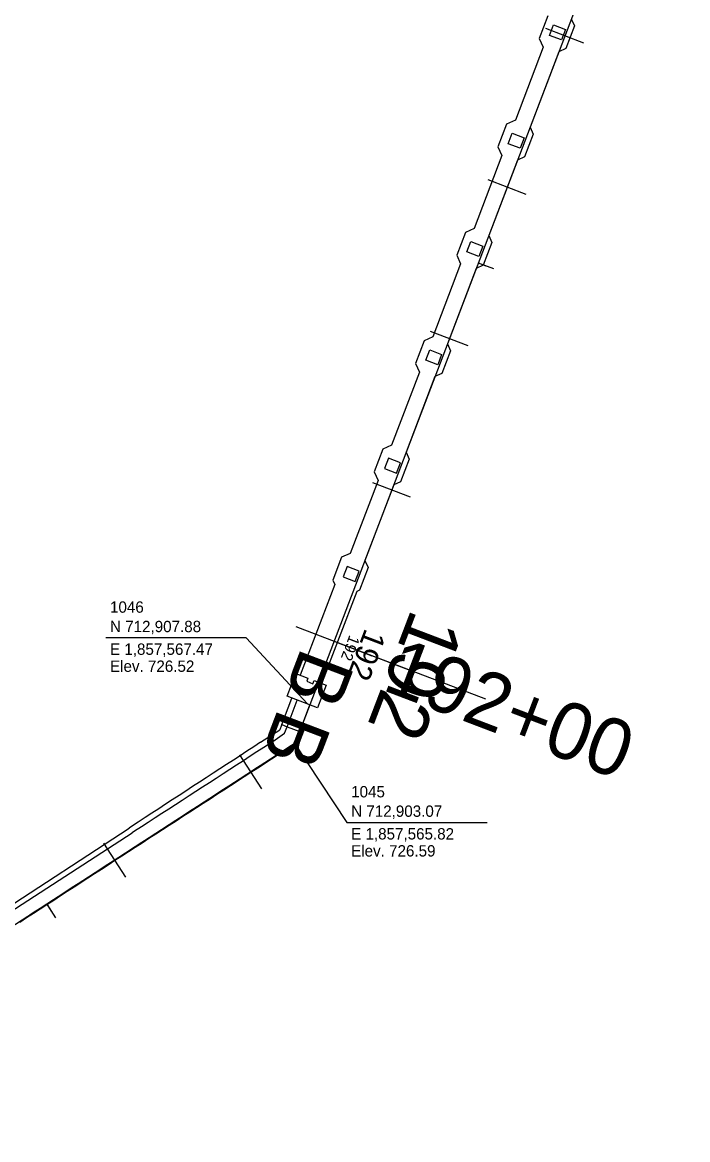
# Model space of a CAD drawing. Extents: x 1823824 to 1861612, y 706975 to 726130.
# Drawn here: x 1826063.6 to 1826145.7, y 712891 to 713028.9 of the extents above; entities that cross this region are included whole.
import ezdxf

# ---------------------------------------------------------------- set-up
doc = ezdxf.new("R2010")
doc.units = 0
for name, color, linetype in [('DR_X_Flood_Boundary', 7, 'Continuous'), ('GE_X_CL_10', 7, 'Continuous'), ('GE_X_CL_100', 7, 'Continuous'), ('GE_X_CL_20', 7, 'Continuous'), ('GE_X_CL_200', 7, 'Continuous'), ('GE_X_CL_50', 7, 'Continuous'), ('SC_Scratch1', 7, 'Continuous'), ('SC_Scratch5', 7, 'Continuous'), ('SC_Scratch6', 7, 'Continuous')]:
    doc.layers.add(name, color=color, linetype=linetype)

msp = doc.modelspace()

# ---------------------------------------------------------------- linework, layer by layer
at = {"layer": 'DR_X_Flood_Boundary'}
for p, q in [((1826145.66, 713067.04), (1826100.09, 712947.43)), ((1826100.09, 712947.43), (1826097.23, 712939.91)), ((1826097.23, 712939.91), (1826021.74, 712890.95))]:
    msp.add_line(p, q, dxfattribs=at)
at = {"layer": 'GE_X_CL_10'}
for p, q in [((1826119.82, 712999.21), (1826120.75, 712998.85)), ((1826102.02, 712952.48), (1826102.95, 712952.13)), ((1826066.57, 712920.02), (1826067.11, 712919.18))]:
    msp.add_line(p, q, dxfattribs=at)
at = {"layer": 'GE_X_CL_100'}
msp.add_line((1826102.02, 712952.48), (1826111.36, 712948.92), dxfattribs=at)
at = {"layer": 'GE_X_CL_20'}
for p, q in [((1826119.82, 712999.21), (1826121.69, 712998.5)), ((1826102.02, 712952.48), (1826103.89, 712951.77)), ((1826066.57, 712920.02), (1826067.66, 712918.35))]:
    msp.add_line(p, q, dxfattribs=at)
at = {"layer": 'GE_X_CL_200'}
msp.add_line((1826102.02, 712952.48), (1826120.71, 712945.36), dxfattribs=at)
at = {"layer": 'GE_X_CL_50'}
msp.add_line((1826102.02, 712952.48), (1826106.69, 712950.7), dxfattribs=at)
at = {"layer": 'SC_Scratch1'}
for p, q in [((1826128.42, 713029.71), (1826127.35, 713026.91)), ((1826128.61, 713027.29), (1826129.1, 713028.58)), ((1826129.1, 713028.58), (1826130.58, 713028.02)), ((1826130.58, 713028.02), (1826130.09, 713026.73)), ((1826131.69, 713028.46), (1826130.62, 713025.66)), ((1826131.3, 713029.32), (1826131.69, 713028.46)), ((1826127.35, 713026.91), (1826127.83, 713025.83)), ((1826130.09, 713026.73), (1826128.61, 713027.29)), ((1826127.83, 713025.83), (1826124.4, 713016.82)), ((1826129.76, 713025.27), (1826126.21, 713015.95)), ((1826130.62, 713025.66), (1826129.76, 713025.27)), ((1826123.32, 713016.34), (1826122.25, 713013.53)), ((1826124.4, 713016.82), (1826123.32, 713016.34)), ((1826126.21, 713015.95), (1826126.59, 713015.09)), ((1826123.52, 713013.92), (1826124, 713015.21)), ((1826124, 713015.21), (1826125.48, 713014.64)), ((1826125.48, 713014.64), (1826124.99, 713013.36)), ((1826126.59, 713015.09), (1826125.52, 713012.29)), ((1826122.25, 713013.53), (1826122.74, 713012.46)), ((1826124.99, 713013.36), (1826123.52, 713013.92)), ((1826122.74, 713012.46), (1826119.3, 713003.45)), ((1826124.66, 713011.9), (1826121.11, 713002.58)), ((1826125.52, 713012.29), (1826124.66, 713011.9)), ((1826119.3, 713003.45), (1826118.23, 713002.96)), ((1826118.23, 713002.96), (1826117.16, 713000.16)), ((1826118.42, 713000.55), (1826118.91, 713001.83)), ((1826118.91, 713001.83), (1826120.39, 713001.27)), ((1826121.11, 713002.58), (1826121.5, 713001.72)), ((1826119.9, 712999.99), (1826118.42, 713000.55)), ((1826120.39, 713001.27), (1826119.9, 712999.99)), ((1826121.5, 713001.72), (1826120.43, 712998.92)), ((1826117.64, 712999.09), (1826114.21, 712990.07)), ((1826117.16, 713000.16), (1826117.64, 712999.09)), ((1826119.57, 712998.53), (1826116.02, 712989.21)), ((1826120.43, 712998.92), (1826119.57, 712998.53)), ((1826113.13, 712989.59), (1826112.06, 712986.79)), ((1826114.21, 712990.07), (1826113.13, 712989.59)), ((1826113.33, 712987.18), (1826113.82, 712988.46)), ((1826113.82, 712988.46), (1826115.3, 712987.9)), ((1826116.4, 712988.35), (1826115.34, 712985.54)), ((1826116.02, 712989.21), (1826116.4, 712988.35)), ((1826112.06, 712986.79), (1826112.55, 712985.71)), ((1826114.81, 712986.61), (1826113.33, 712987.18)), ((1826115.3, 712987.9), (1826114.81, 712986.61)), ((1826112.55, 712985.71), (1826109.11, 712976.7)), ((1826115.34, 712985.54), (1826114.47, 712985.16)), ((1826114.47, 712985.16), (1826110.92, 712975.83)), ((1826108.04, 712976.22), (1826106.97, 712973.42)), ((1826109.11, 712976.7), (1826108.04, 712976.22)), ((1826110.92, 712975.83), (1826111.31, 712974.97)), ((1826108.72, 712975.09), (1826108.23, 712973.8)), ((1826110.2, 712974.53), (1826108.72, 712975.09)), ((1826109.71, 712973.24), (1826110.2, 712974.53)), ((1826111.31, 712974.97), (1826110.24, 712972.17)), ((1826106.97, 712973.42), (1826107.45, 712972.34)), ((1826108.23, 712973.8), (1826109.71, 712973.24)), ((1826107.45, 712972.34), (1826104.02, 712963.33)), ((1826109.38, 712971.78), (1826105.83, 712962.46)), ((1826110.24, 712972.17), (1826109.38, 712971.78)), ((1826104.02, 712963.33), (1826102.94, 712962.85)), ((1826104.02, 712963.33), (1826104.02, 712963.33)), ((1826102.94, 712962.85), (1826101.88, 712960.04)), ((1826105.83, 712962.46), (1826106.22, 712961.6)), ((1826103.63, 712961.72), (1826103.14, 712960.43)), ((1826103.14, 712960.43), (1826104.62, 712959.87)), ((1826105.11, 712961.15), (1826103.63, 712961.72)), ((1826104.62, 712959.87), (1826105.11, 712961.15)), ((1826106.22, 712961.6), (1826105.15, 712958.8)), ((1826102.11, 712959.5), (1826097.85, 712948.29)), ((1826101.88, 712960.04), (1826102.12, 712959.51)), ((1826102.12, 712959.51), (1826102.11, 712959.5)), ((1826104.82, 712958.65), (1826100.49, 712947.28)), ((1826105.15, 712958.8), (1826104.82, 712958.65)), ((1826104.82, 712958.65), (1826104.82, 712958.65)), ((1826096.23, 712945.69), (1826097.3, 712948.49)), ((1826097.3, 712948.49), (1826098.79, 712947.92)), ((1826098.79, 712947.92), (1826098.64, 712947.54)), ((1826098.64, 712947.54), (1826099.4, 712947.25)), ((1826099.4, 712947.25), (1826099.55, 712947.64)), ((1826099.55, 712947.64), (1826101.03, 712947.07)), ((1826101.03, 712947.07), (1826099.97, 712944.26)), ((1826095.56, 712942.2), (1826096.81, 712945.47)), ((1826099.97, 712944.26), (1826096.23, 712945.69)), ((1826096.23, 712941.94), (1826097.47, 712945.21)), ((1826097.79, 712941.35), (1826099.03, 712944.62)), ((1826092.94, 712940.01), (1826095.33, 712941.57)), ((1826094.46, 712940.1), (1826095.91, 712941.12)), ((1826095.91, 712941.12), (1826096.23, 712941.94)), ((1826058.32, 712917.37), (1826076.72, 712929.43)), ((1826058.65, 712916.86), (1826077.1, 712928.84))]:
    msp.add_line(p, q, dxfattribs=at)
for points in [[(1826098.73, 712944.75), (1826091.16, 712952.91), (1826073.85, 712952.91)], [(1826098.73, 712944.75), (1826091.16, 712952.91), (1826073.85, 712952.91)], [(1826097.78, 712941.35), (1826097.75, 712941.27), (1826097.39, 712940.34), (1826097.23, 712939.91), (1826096.77, 712939.61), (1826095.93, 712939.07), (1826095.09, 712938.52), (1826094.25, 712937.98), (1826093.42, 712937.44), (1826092.58, 712936.89), (1826091.74, 712936.35), (1826090.9, 712935.8), (1826090.06, 712935.26), (1826089.22, 712934.72), (1826088.38, 712934.17), (1826087.54, 712933.63), (1826086.7, 712933.08), (1826085.86, 712932.54), (1826085.03, 712931.99), (1826084.19, 712931.45), (1826083.35, 712930.91), (1826082.51, 712930.36), (1826081.67, 712929.82), (1826080.83, 712929.27), (1826079.99, 712928.73), (1826079.15, 712928.19), (1826078.31, 712927.64), (1826077.47, 712927.1), (1826076.64, 712926.55), (1826075.8, 712926.01), (1826074.96, 712925.46), (1826074.12, 712924.92), (1826073.28, 712924.38), (1826072.44, 712923.83), (1826071.6, 712923.29), (1826070.76, 712922.74), (1826069.92, 712922.2), (1826069.08, 712921.66), (1826068.25, 712921.11), (1826067.41, 712920.57), (1826066.57, 712920.02), (1826065.73, 712919.48), (1826064.89, 712918.94), (1826064.05, 712918.39), (1826063.21, 712917.85)], [(1826095.11, 712938.49), (1826095.95, 712939.04), (1826096.79, 712939.58), (1826097.26, 712939.89), (1826097.43, 712940.32), (1826097.78, 712941.26), (1826097.82, 712941.34)], [(1826095.56, 712942.2), (1826095.53, 712942.11), (1826095.33, 712941.57)], [(1826095.56, 712942.2), (1826096.23, 712941.94), (1826097.78, 712941.35), (1826097.81, 712941.34)], [(1826092.94, 712940.01), (1826092.1, 712939.46), (1826091.27, 712938.91), (1826090.43, 712938.36), (1826089.59, 712937.82), (1826088.76, 712937.27), (1826087.92, 712936.72), (1826087.08, 712936.18), (1826086.24, 712935.63), (1826085.4, 712935.09), (1826084.57, 712934.54), (1826083.73, 712933.99), (1826082.89, 712933.45), (1826082.05, 712932.9), (1826081.22, 712932.36), (1826080.38, 712931.81), (1826079.54, 712931.26), (1826078.7, 712930.72), (1826077.86, 712930.17), (1826077.03, 712929.63), (1826076.72, 712929.43)], [(1826094.46, 712940.1), (1826094.19, 712939.92), (1826093.35, 712939.37), (1826092.51, 712938.83), (1826091.67, 712938.28), (1826090.83, 712937.74), (1826090, 712937.2), (1826089.16, 712936.65), (1826088.32, 712936.11), (1826087.48, 712935.56), (1826086.64, 712935.02), (1826085.8, 712934.48), (1826084.96, 712933.93), (1826084.12, 712933.39), (1826083.28, 712932.84), (1826082.44, 712932.3), (1826081.61, 712931.76), (1826080.77, 712931.21), (1826079.93, 712930.67), (1826079.09, 712930.12), (1826078.25, 712929.58), (1826077.41, 712929.03), (1826077.1, 712928.84)], [(1826097.08, 712939.94), (1826103.61, 712930.11), (1826120.92, 712930.11)], [(1826097.08, 712939.94), (1826103.61, 712930.11), (1826120.92, 712930.11)], [(1826063.23, 712917.82), (1826064.07, 712918.37), (1826064.91, 712918.91), (1826065.75, 712919.45), (1826066.58, 712920), (1826067.42, 712920.54), (1826068.26, 712921.09), (1826069.1, 712921.63), (1826069.94, 712922.17), (1826070.78, 712922.72), (1826071.62, 712923.26), (1826072.46, 712923.81), (1826073.3, 712924.35), (1826074.14, 712924.89), (1826074.98, 712925.44), (1826075.81, 712925.98), (1826076.65, 712926.53), (1826077.49, 712927.07), (1826078.33, 712927.61), (1826079.17, 712928.16), (1826080.01, 712928.7), (1826080.85, 712929.25), (1826081.69, 712929.79), (1826082.53, 712930.33), (1826083.37, 712930.88), (1826084.21, 712931.42), (1826085.04, 712931.97), (1826085.88, 712932.51), (1826086.72, 712933.05), (1826087.56, 712933.6), (1826088.4, 712934.14), (1826089.24, 712934.69), (1826090.08, 712935.23), (1826090.92, 712935.77), (1826091.76, 712936.32), (1826092.6, 712936.86), (1826093.44, 712937.4), (1826094.28, 712937.95), (1826095.11, 712938.49)]]:
    msp.add_lwpolyline(points, dxfattribs=at)
at = {"layer": 'SC_Scratch5'}
for points in [[(1826132.83, 713026.35), (1826128.16, 713028.13)], [(1826125.71, 713007.66), (1826121.04, 713009.44)], [(1826118.59, 712988.97), (1826113.92, 712990.75)], [(1826111.47, 712970.28), (1826106.8, 712972.06)], [(1826106.69, 712950.7), (1826097.34, 712954.26)], [(1826093.1, 712934.25), (1826090.38, 712938.45)], [(1826076.32, 712923.37), (1826073.6, 712927.56)]]:
    msp.add_lwpolyline(points, dxfattribs=at)

# ---------------------------------------------------------------- texts
at = {"layer": 'GE_X_CL_10'}
msp.add_text('192', height=1.4, rotation=249.1458, dxfattribs=at).set_placement((1826103.94, 712953.33))
at = {"layer": 'GE_X_CL_20'}
msp.add_text('192', height=2.8, rotation=249.1458, dxfattribs=at).set_placement((1826105.87, 712954.17))
at = {"layer": 'GE_X_CL_50'}
msp.add_text('192', height=7, rotation=249.1458, dxfattribs=at).set_placement((1826111.64, 712956.69))
at = {"layer": 'SC_Scratch1'}
for s, p in [(' 1046', (1826073.85, 712956.01)), (' 1046', (1826073.85, 712956.01)), (' N 712,907.88', (1826073.85, 712953.61)), (' N 712,907.88', (1826073.85, 712953.61)), (' E 1,857,567.47', (1826073.85, 712950.81)), (' E 1,857,567.47', (1826073.85, 712950.81)), (' Elev. 726.52 ', (1826073.85, 712948.71)), (' Elev. 726.52 ', (1826073.85, 712948.71)), (' 1045', (1826103.61, 712933.21)), (' 1045', (1826103.61, 712933.21)), (' N 712,903.07', (1826103.61, 712930.81)), (' N 712,903.07', (1826103.61, 712930.81)), (' E 1,857,565.82', (1826103.61, 712928.01)), (' E 1,857,565.82', (1826103.61, 712928.01)), (' Elev. 726.59 ', (1826103.61, 712925.91)), (' Elev. 726.59 ', (1826103.61, 712925.91))]:
    msp.add_text(s, height=1.4, dxfattribs=at).set_placement(p)
at = {"layer": 'SC_Scratch5'}
msp.add_text('192+00', height=7, rotation=339.1458, dxfattribs=at).set_placement((1826107.78, 712946.54))
at = {"layer": 'SC_Scratch6'}
for rotation, p in [(249.1458, (1826098.07, 712951.95)), (249.1415, (1826095.2, 712944.42))]:
    msp.add_text('B', height=7, rotation=rotation, dxfattribs=at).set_placement(p)

doc.saveas('drawing.dxf')
